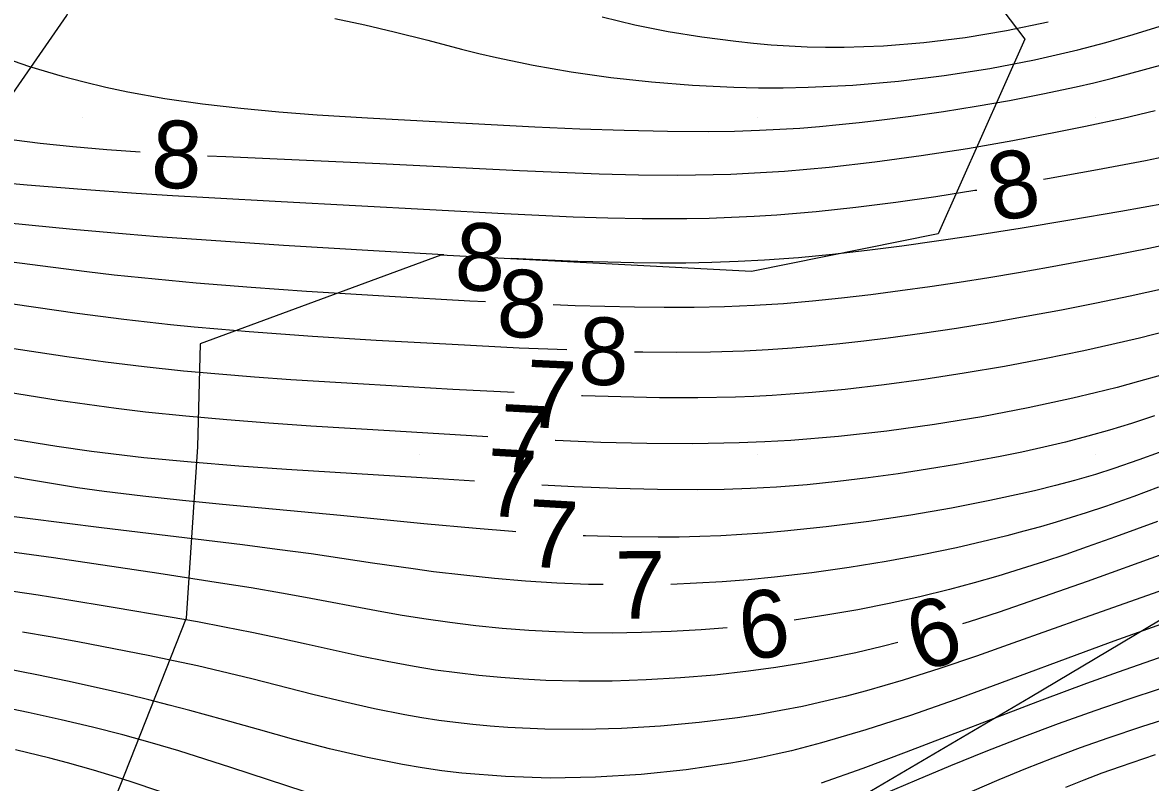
# Model space of a CAD drawing. Extents: x 2602990 to 2605851, y 618069 to 619180.
# Drawn here: x 2603268.24 to 2603301.63, y 618610.3 to 618632.8 of the extents above; entities that cross this region are included whole.
import ezdxf

# ---------------------------------------------------------------- set-up
doc = ezdxf.new("R2010")
doc.units = 0
for name, color, linetype in [('DTM Contours Major', 7, 'Continuous'), ('DTM Contours Major Text', 7, 'Continuous'), ('DTM Contours Minor', 7, 'Continuous'), ('DTM Contours Minor Text', 7, 'Continuous'), ('Exist DTM Crownline', 7, 'Continuous'), ('Exist DTM QL2 LIDAR Elevation Point', 7, 'Continuous'), ('Exist Roads EOP', 7, 'Continuous'), ('PH Exist DTM Obscure Area', 7, 'Continuous')]:
    doc.layers.add(name, color=color, linetype=linetype)

msp = doc.modelspace()

# ---------------------------------------------------------------- linework, layer by layer
at = {"layer": 'DTM Contours Major'}
for points in [[(2603302.068, 618627.447), (2603300.753, 618627.206), (2603299.244, 618626.945), (2603297.774, 618626.705), (2603296.319, 618626.48), (2603295.292, 618626.328), (2603294.264, 618626.184), (2603293.238, 618626.052), (2603292.218, 618625.936), (2603291.206, 618625.838), (2603290.205, 618625.763), (2603289.42, 618625.721), (2603288.643, 618625.694), (2603287.87, 618625.681), (2603287.101, 618625.679), (2603286.334, 618625.687), (2603285.566, 618625.703), (2603284.671, 618625.729), (2603283.775, 618625.764), (2603282.703, 618625.815)], [(2603280.706, 618625.921), (2603278.797, 618626.029), (2603275.962, 618626.202), (2603274.107, 618626.323), (2603272.236, 618626.458), (2603271.302, 618626.533), (2603269.723, 618626.675), (2603267.113, 618626.927)], [(2603302.377, 618616.135), (2603299.664, 618615.179), (2603297.553, 618614.424), (2603296.473, 618614.044), (2603295.387, 618613.677), (2603294.302, 618613.332), (2603293.225, 618613.018), (2603292.589, 618612.85), (2603291.956, 618612.696), (2603291.324, 618612.556), (2603290.688, 618612.429), (2603290.048, 618612.316), (2603289.399, 618612.216), (2603288.27, 618612.074), (2603287.123, 618611.968), (2603285.97, 618611.901), (2603284.823, 618611.872), (2603283.695, 618611.881), (2603282.598, 618611.93), (2603282.077, 618611.969), (2603281.564, 618612.017), (2603281.057, 618612.074), (2603280.556, 618612.142), (2603280.057, 618612.219), (2603279.558, 618612.305), (2603278.652, 618612.486), (2603277.743, 618612.691), (2603276.834, 618612.912), (2603275.022, 618613.369), (2603274.121, 618613.588), (2603273.413, 618613.752), (2603272.708, 618613.906), (2603272.003, 618614.053), (2603271.297, 618614.194), (2603269.877, 618614.463), (2603269.059, 618614.611), (2603268.234, 618614.752)]]:
    msp.add_lwpolyline(points, dxfattribs=at)
at = {"layer": 'DTM Contours Minor'}
for points in [[(2603277.485, 618632.917), (2603278.37, 618632.73), (2603279.242, 618632.529), (2603280.237, 618632.275), (2603281.235, 618632.014), (2603281.745, 618631.886), (2603282.266, 618631.763), (2603283.348, 618631.538), (2603284.48, 618631.342), (2603285.651, 618631.177), (2603286.851, 618631.045), (2603288.068, 618630.949), (2603289.292, 618630.889), (2603290.021, 618630.872), (2603290.752, 618630.869), (2603291.492, 618630.883), (2603292.818, 618630.949), (2603294.166, 618631.065), (2603295.522, 618631.23), (2603296.87, 618631.441), (2603298.194, 618631.696), (2603299.477, 618631.992), (2603300.309, 618632.212), (2603301.118, 618632.447), (2603301.91, 618632.694)], [(2603285.397, 618632.969), (2603286.363, 618632.732), (2603287.349, 618632.535), (2603288.346, 618632.374), (2603289.348, 618632.246), (2603289.874, 618632.19), (2603290.401, 618632.144), (2603290.932, 618632.108), (2603291.467, 618632.083), (2603292.01, 618632.069), (2603292.562, 618632.069), (2603293.723, 618632.11), (2603294.919, 618632.208), (2603296.139, 618632.36), (2603297.369, 618632.566), (2603298.597, 618632.824)], [(2603267.465, 618631.83), (2603268.439, 618631.503), (2603269.413, 618631.211), (2603270.057, 618631.04), (2603270.704, 618630.886), (2603271.356, 618630.748), (2603272.451, 618630.553), (2603273.566, 618630.393), (2603274.694, 618630.262), (2603275.826, 618630.157), (2603276.955, 618630.07), (2603278.452, 618629.975), (2603280.815, 618629.846), (2603283.404, 618629.714), (2603284.732, 618629.657), (2603286.049, 618629.611), (2603287.329, 618629.583), (2603288.547, 618629.576), (2603289.314, 618629.587), (2603290.052, 618629.61), (2603290.654, 618629.639), (2603291.246, 618629.678), (2603291.832, 618629.725), (2603292.416, 618629.78), (2603293.003, 618629.843), (2603293.598, 618629.913), (2603294.536, 618630.032), (2603295.495, 618630.169), (2603296.471, 618630.322), (2603297.456, 618630.494), (2603298.444, 618630.686), (2603299.429, 618630.899), (2603299.946, 618631.02), (2603300.463, 618631.147), (2603300.981, 618631.281), (2603302.03, 618631.567)], [(2603301.769, 618630.184), (2603300.818, 618629.961), (2603299.707, 618629.721), (2603298.867, 618629.55), (2603297.556, 618629.301), (2603296.208, 618629.066), (2603294.841, 618628.852), (2603293.472, 618628.664), (2603292.118, 618628.509), (2603290.797, 618628.392), (2603290.26, 618628.356), (2603289.73, 618628.327), (2603289.204, 618628.305), (2603288.68, 618628.29), (2603288.157, 618628.28), (2603287.632, 618628.276), (2603286.473, 618628.285), (2603285.302, 618628.313), (2603284.124, 618628.357), (2603282.947, 618628.411), (2603278.817, 618628.62), (2603274.251, 618628.82), (2603273.716, 618628.846)], [(2603271.719, 618628.959), (2603270.727, 618629.029), (2603269.723, 618629.117), (2603268.757, 618629.22), (2603267.987, 618629.317)], [(2603302.42, 618628.904), (2603301.484, 618628.71), (2603300.058, 618628.439), (2603298.577, 618628.177), (2603298.459, 618628.157)], [(2603296.485, 618627.832), (2603296.432, 618627.823), (2603295.269, 618627.645), (2603294.089, 618627.477), (2603292.903, 618627.327), (2603291.726, 618627.199), (2603290.569, 618627.1), (2603289.891, 618627.056), (2603289.222, 618627.024), (2603288.56, 618627.003), (2603287.901, 618626.991), (2603287.243, 618626.987), (2603286.583, 618626.991), (2603285.565, 618627.01), (2603284.541, 618627.042), (2603283.516, 618627.084), (2603282.495, 618627.133), (2603275.894, 618627.494), (2603273.756, 618627.609), (2603272.677, 618627.672), (2603271.601, 618627.739), (2603269.993, 618627.853), (2603268.376, 618627.986), (2603265.027, 618628.287)], [(2603302.733, 618626.359), (2603301.578, 618626.114), (2603300.423, 618625.884), (2603299.513, 618625.712), (2603298.613, 618625.548), (2603297.722, 618625.393), (2603296.839, 618625.247), (2603295.964, 618625.108), (2603295.095, 618624.978), (2603294.22, 618624.854), (2603293.35, 618624.74), (2603292.485, 618624.638), (2603291.622, 618624.549), (2603290.762, 618624.477), (2603289.902, 618624.421), (2603289.012, 618624.384), (2603288.122, 618624.364), (2603287.235, 618624.36), (2603286.35, 618624.369), (2603285.47, 618624.389), (2603284.594, 618624.416), (2603283.942, 618624.443)], [(2603281.944, 618624.533), (2603281.473, 618624.556), (2603279.103, 618624.688), (2603276.639, 618624.84), (2603275, 618624.956), (2603273.375, 618625.087), (2603272.564, 618625.16), (2603271.755, 618625.239), (2603270.946, 618625.326), (2603270.139, 618625.42), (2603267.136, 618625.805)], [(2603302.016, 618624.917), (2603301.028, 618624.697), (2603300.031, 618624.489), (2603298.992, 618624.285), (2603297.951, 618624.093), (2603296.914, 618623.913), (2603295.885, 618623.747), (2603294.867, 618623.595), (2603293.866, 618623.458), (2603293.145, 618623.368), (2603292.432, 618623.287), (2603291.723, 618623.217), (2603291.017, 618623.157), (2603290.31, 618623.108), (2603289.598, 618623.071), (2603288.604, 618623.041), (2603287.601, 618623.032), (2603286.595, 618623.04), (2603286.351, 618623.046)], [(2603284.352, 618623.106), (2603282.942, 618623.165), (2603280.959, 618623.265), (2603278.703, 618623.391), (2603276.821, 618623.508), (2603275.881, 618623.573), (2603274.946, 618623.643), (2603274.021, 618623.72), (2603273.317, 618623.784), (2603272.619, 618623.853), (2603271.926, 618623.927), (2603271.235, 618624.007), (2603270.545, 618624.093), (2603269.853, 618624.186), (2603267.329, 618624.55)], [(2603302.115, 618623.662), (2603301.306, 618623.457), (2603300.485, 618623.264), (2603299.651, 618623.08), (2603298.485, 618622.842), (2603297.301, 618622.62), (2603296.11, 618622.416), (2603294.921, 618622.234), (2603293.745, 618622.075), (2603292.593, 618621.941), (2603292.045, 618621.886), (2603291.503, 618621.838), (2603290.964, 618621.796), (2603290.426, 618621.761), (2603289.888, 618621.733), (2603289.346, 618621.712), (2603288.225, 618621.69), (2603287.091, 618621.692), (2603285.951, 618621.715), (2603284.813, 618621.752), (2603284.788, 618621.753)], [(2603282.79, 618621.847), (2603280.979, 618621.94), (2603278.326, 618622.091), (2603276.18, 618622.226), (2603275.108, 618622.303), (2603274.047, 618622.388), (2603273.006, 618622.483), (2603271.84, 618622.606), (2603270.692, 618622.746), (2603269.543, 618622.905), (2603267.651, 618623.193)], [(2603301.912, 618622.353), (2603301.277, 618622.17), (2603300.637, 618621.997), (2603299.988, 618621.834), (2603299.328, 618621.678), (2603298.005, 618621.392), (2603296.637, 618621.132), (2603295.238, 618620.903), (2603293.82, 618620.706), (2603292.396, 618620.548), (2603290.979, 618620.431), (2603290.213, 618620.386), (2603289.449, 618620.354), (2603288.083, 618620.328), (2603286.718, 618620.336), (2603285.359, 618620.371), (2603284.013, 618620.426), (2603284.006, 618620.427)], [(2603282.009, 618620.535), (2603279.269, 618620.699), (2603276.774, 618620.855), (2603275.526, 618620.942), (2603274.288, 618621.038), (2603273.069, 618621.147), (2603271.879, 618621.27), (2603271.009, 618621.374), (2603270.15, 618621.489), (2603269.293, 618621.614), (2603267.139, 618621.957)], [(2603301.749, 618621.156), (2603301.068, 618620.932), (2603300.413, 618620.732), (2603299.777, 618620.553), (2603299.116, 618620.38), (2603298.466, 618620.225), (2603297.822, 618620.083), (2603297.181, 618619.953), (2603296.537, 618619.832), (2603295.887, 618619.717), (2603295.029, 618619.574), (2603294.156, 618619.44), (2603293.269, 618619.318), (2603292.372, 618619.21), (2603291.466, 618619.119), (2603290.553, 618619.049), (2603289.786, 618619.006), (2603289.007, 618618.979), (2603288.21, 618618.967), (2603287.038, 618618.974), (2603285.821, 618619.006), (2603284.568, 618619.057), (2603283.61, 618619.107)], [(2603281.614, 618619.224), (2603280.698, 618619.279), (2603276.055, 618619.568), (2603274.644, 618619.667), (2603273.231, 618619.781), (2603271.826, 618619.918), (2603270.278, 618620.103), (2603269.25, 618620.25), (2603267.967, 618620.457)], [(2603301.881, 618620.069), (2603301.286, 618619.851), (2603300.538, 618619.594), (2603300.002, 618619.425), (2603299.373, 618619.241), (2603298.817, 618619.091), (2603298.231, 618618.946), (2603297.924, 618618.874), (2603296.872, 618618.646), (2603295.732, 618618.426), (2603294.528, 618618.219), (2603293.286, 618618.032), (2603292.031, 618617.87), (2603290.788, 618617.739), (2603290.154, 618617.685), (2603289.528, 618617.641), (2603288.908, 618617.607), (2603288.29, 618617.582), (2603287.674, 618617.567), (2603287.056, 618617.561), (2603285.98, 618617.572), (2603284.898, 618617.606), (2603284.837, 618617.609)], [(2603282.841, 618617.725), (2603282.737, 618617.732), (2603281.667, 618617.818), (2603280.119, 618617.962), (2603277.652, 618618.21), (2603274.153, 618618.533), (2603272.97, 618618.65), (2603271.799, 618618.777), (2603270.653, 618618.919), (2603269.866, 618619.03), (2603269.09, 618619.151), (2603268.321, 618619.28), (2603267.294, 618619.465)], [(2603301.869, 618619.042), (2603301.139, 618618.771), (2603300.294, 618618.476), (2603299.72, 618618.287), (2603299.284, 618618.149), (2603298.834, 618618.011), (2603298.367, 618617.875), (2603297.882, 618617.74), (2603297.375, 618617.606), (2603296.845, 618617.474), (2603295.885, 618617.254), (2603294.865, 618617.044), (2603293.8, 618616.848), (2603292.707, 618616.669), (2603291.602, 618616.513), (2603290.499, 618616.381), (2603289.722, 618616.306), (2603288.952, 618616.245), (2603288.189, 618616.199), (2603287.432, 618616.168), (2603287.426, 618616.168)], [(2603285.426, 618616.16), (2603284.99, 618616.168), (2603284.057, 618616.207), (2603283.129, 618616.266), (2603282.21, 618616.342), (2603281.301, 618616.435), (2603280.404, 618616.543), (2603279.8, 618616.624), (2603278.601, 618616.798), (2603276.78, 618617.067), (2603275.775, 618617.204), (2603274.75, 618617.335), (2603270.578, 618617.841), (2603268.38, 618618.12), (2603267.261, 618618.252)], [(2603301.839, 618618.024), (2603300.596, 618617.571), (2603299.754, 618617.275), (2603299.117, 618617.056), (2603298.465, 618616.838), (2603297.796, 618616.623), (2603297.109, 618616.412), (2603296.403, 618616.209), (2603295.676, 618616.013), (2603294.795, 618615.798), (2603293.888, 618615.598), (2603292.961, 618615.416), (2603292.02, 618615.252), (2603291.079, 618615.111)], [(2603289.092, 618614.885), (2603288.329, 618614.823), (2603287.441, 618614.77), (2603286.56, 618614.738), (2603285.687, 618614.726), (2603284.823, 618614.735), (2603284.018, 618614.761), (2603283.223, 618614.805), (2603282.435, 618614.865), (2603281.656, 618614.943), (2603280.884, 618615.036), (2603280.119, 618615.145), (2603279.418, 618615.258), (2603278.719, 618615.381), (2603276.615, 618615.776), (2603275.904, 618615.906), (2603275.008, 618616.06), (2603274.101, 618616.206), (2603272.27, 618616.485), (2603269.15, 618616.949), (2603268.503, 618617.042), (2603267.851, 618617.129)], [(2603301.994, 618617.062), (2603299.749, 618616.254), (2603298.03, 618615.647), (2603297.151, 618615.347), (2603296.262, 618615.057), (2603296.067, 618614.997)], [(2603294.146, 618614.444), (2603293.687, 618614.326), (2603292.909, 618614.144), (2603292.125, 618613.98), (2603291.335, 618613.834), (2603290.538, 618613.706), (2603289.732, 618613.595), (2603288.727, 618613.482), (2603287.715, 618613.396), (2603286.702, 618613.338), (2603285.696, 618613.306), (2603284.703, 618613.302), (2603283.729, 618613.326), (2603283.059, 618613.36), (2603282.399, 618613.407), (2603281.748, 618613.469), (2603281.103, 618613.544), (2603280.463, 618613.632), (2603279.825, 618613.735), (2603279.028, 618613.881), (2603278.231, 618614.043), (2603276.63, 618614.394), (2603275.827, 618614.571), (2603275.02, 618614.744), (2603274.217, 618614.905), (2603273.411, 618615.057), (2603272.602, 618615.201), (2603270.98, 618615.476), (2603269.432, 618615.729), (2603268.695, 618615.845), (2603267.954, 618615.954)], [(2603303.667, 618615.602), (2603300.542, 618614.482), (2603299.715, 618614.182), (2603297.162, 618613.233), (2603295.847, 618612.752), (2603294.522, 618612.288), (2603293.2, 618611.857), (2603291.891, 618611.473), (2603291.443, 618611.354), (2603290.996, 618611.243), (2603290.55, 618611.139), (2603290.103, 618611.043), (2603289.655, 618610.953), (2603289.204, 618610.871), (2603287.885, 618610.674), (2603286.545, 618610.535), (2603285.197, 618610.455), (2603283.856, 618610.435), (2603282.534, 618610.476), (2603281.245, 618610.579), (2603280.651, 618610.649), (2603280.064, 618610.733), (2603279.483, 618610.83), (2603278.398, 618611.048), (2603277.324, 618611.301), (2603276.264, 618611.578), (2603275.22, 618611.867), (2603274.193, 618612.156), (2603273.187, 618612.434), (2603272.577, 618612.596), (2603271.973, 618612.749), (2603271.373, 618612.896), (2603270.773, 618613.036), (2603269.566, 618613.303), (2603268.663, 618613.49), (2603267.75, 618613.665)], [(2603304.19, 618614.798), (2603300.668, 618613.568), (2603299.734, 618613.231), (2603298.406, 618612.735), (2603294.392, 618611.195), (2603293.107, 618610.718), (2603291.881, 618610.287)], [(2603301.917, 618613.078), (2603300.952, 618612.759), (2603299.979, 618612.427), (2603298.895, 618612.039), (2603297.817, 618611.635), (2603296.753, 618611.219), (2603295.711, 618610.798), (2603294.698, 618610.374), (2603293.725, 618609.953)], [(2603276.602, 618610.029), (2603274.4, 618610.75), (2603273.637, 618610.996), (2603272.863, 618611.236), (2603272.079, 618611.468), (2603271.201, 618611.71), (2603270.305, 618611.94), (2603269.38, 618612.16), (2603268.403, 618612.376), (2603267.4, 618612.577)], [(2603302.354, 618612.266), (2603301.357, 618611.948), (2603300.366, 618611.617), (2603299.546, 618611.328), (2603298.735, 618611.025), (2603297.931, 618610.709), (2603297.133, 618610.379), (2603296.338, 618610.035)], [(2603272.3, 618610.034), (2603271.45, 618610.322), (2603271.018, 618610.461), (2603270.333, 618610.669), (2603269.571, 618610.885), (2603269.04, 618611.025), (2603268.024, 618611.273)], [(2603301.77, 618611.125), (2603300.729, 618610.77), (2603300.189, 618610.574), (2603299.652, 618610.368), (2603299.115, 618610.152)]]:
    msp.add_lwpolyline(points, dxfattribs=at)
at = {"layer": 'Exist DTM Crownline'}
msp.add_spline([(2603233.488, 618380.754), (2603285.185, 618400.095), (2603335.457, 618418.629), (2603390.812, 618439.069), (2603440.087, 618457.325), (2603493.996, 618477.231), (2603542.655, 618495.301), (2603600.808, 618516.867), (2603653.659, 618536.362), (2603706.222, 618555.742), (2603764.811, 618577.593), (2603823.52, 618599.847), (2603878.564, 618620.56), (2603937.951, 618643.078), (2603997.369, 618665.789), (2604036.209, 618680.665), (2604055.311, 618688.017)], degree=3, dxfattribs=at)
at = {"layer": 'Exist DTM QL2 LIDAR Elevation Point'}
for p, q in [((2603270, 618630), (2603270, 618630)), ((2603280, 618630), (2603280, 618630)), ((2603290, 618630), (2603290, 618630)), ((2603300, 618630), (2603300, 618630)), ((2603270, 618620), (2603270, 618620)), ((2603280, 618620), (2603280, 618620)), ((2603290, 618620), (2603290, 618620)), ((2603300, 618620), (2603300, 618620))]:
    msp.add_line(p, q, dxfattribs=at)
at = {"layer": 'Exist Roads EOP'}
for points in [[(2603230.17, 618389.98), (2603282.929, 618409.597), (2603332.773, 618427.868), (2603388.167, 618448.413), (2603437.203, 618466.721), (2603490.778, 618486.527), (2603539.039, 618504.558), (2603597.451, 618526.156), (2603651.053, 618545.972), (2603705.208, 618566.084), (2603762.02, 618587.183), (2603820.334, 618609.162), (2603876.341, 618629.99), (2603934.909, 618652.28), (2603996.409, 618675.568), (2604033.216, 618689.957), (2604052.01, 618697.199)], [(2604034.633, 618668.486), (2603984.89, 618650.123), (2603936.767, 618631.654), (2603888.195, 618613.335), (2603837.766, 618594.258), (2603782.918, 618573.705), (2603731.939, 618554.39), (2603671.126, 618532.171), (2603621.822, 618514.106), (2603561.545, 618491.877), (2603506.421, 618471.293), (2603452.163, 618451.33), (2603398.364, 618431.316), (2603341.431, 618410.355), (2603281.65, 618388.199), (2603223.033, 618366.475), (2603185.717, 618352.612)]]:
    msp.add_spline(points, degree=3, dxfattribs=at)
at = {"layer": 'PH Exist DTM Obscure Area'}
for points in [[(2603265.087, 618589.76), (2603272.976, 618594.164), (2603276.671, 618597.191), (2603280.942, 618601.168), (2603285.34, 618605.272), (2603290.685, 618608.482), (2603298.066, 618612.825), (2603304.621, 618616.727), (2603312.647, 618623.288), (2603316.448, 618635.135), (2603315.518, 618639.645), (2603317.77, 618646.233), (2603324.356, 618656.735), (2603336.075, 618665.816), (2603339.207, 618670.496), (2603343.226, 618674.918), (2603351.998, 618678.303)], [(2603312.275, 618674.534), (2603312.005, 618674.434), (2603311.545, 618671.137), (2603310.068, 618667.527), (2603307.195, 618663.797), (2603305.011, 618658.287), (2603302.07, 618653.669), (2603297.096, 618648.49), (2603293.652, 618645.017), (2603291.728, 618640.711), (2603294.249, 618637.146), (2603297.906, 618632.306), (2603295.34, 618626.544), (2603289.815, 618625.428), (2603280.616, 618625.917), (2603273.497, 618623.286), (2603273.419, 618620.24), (2603273.077, 618615.166), (2603270.508, 618608.643), (2603262.367, 618604.748)], [(2603265.074, 618626.562), (2603269.546, 618633.013), (2603272.815, 618639.85), (2603273.925, 618646.38), (2603266.771, 618649.714)]]:
    msp.add_lwpolyline(points, dxfattribs=at)

# ---------------------------------------------------------------- texts
at = {"layer": 'DTM Contours Major Text'}
msp.add_text('8', height=2, rotation=356.945, dxfattribs=at).set_placement((2603280.998, 618624.901))
at = {"layer": 'DTM Contours Minor Text'}
for s, rotation, p in [('8', 356.7817, (2603272.008, 618627.937)), ('8', 9.3564, (2603296.99, 618626.899)), ('8', 357.4156, (2603282.245, 618623.514)), ('8', 358.2768, (2603284.668, 618622.091)), ('7', 357.3209, (2603283.09, 618620.828)), ('7', 356.8817, (2603282.301, 618619.515)), ('7', 356.6267, (2603281.901, 618618.204)), ('7', 356.6594, (2603283.128, 618616.699)), ('7', 0.2352, (2603285.777, 618615.149)), ('6', 6.4898, (2603289.551, 618613.918)), ('6', 16.0559, (2603294.758, 618613.567))]:
    msp.add_text(s, height=2, rotation=rotation, dxfattribs=at).set_placement(p)

doc.saveas('drawing.dxf')
